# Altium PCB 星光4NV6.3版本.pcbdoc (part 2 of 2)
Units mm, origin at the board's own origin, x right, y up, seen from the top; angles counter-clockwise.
Board outline 96.4 x 47 mm, 2 copper layers (Top Layer, Bottom Layer), stack 1.58 mm thick; 27 components, 21 nets, 136 pads, 174 vias.
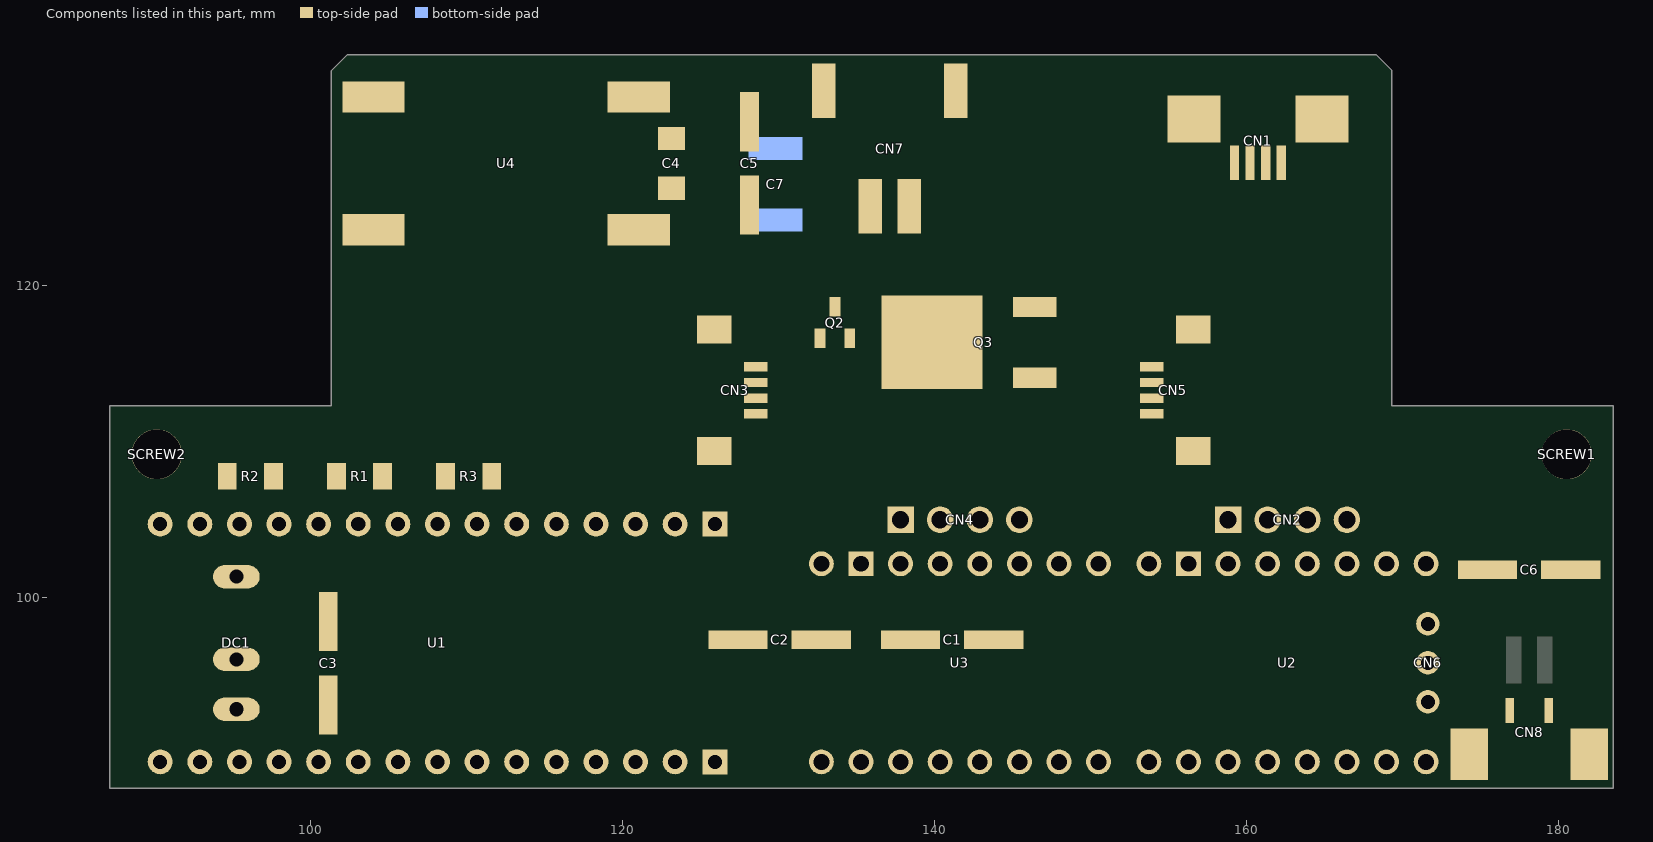
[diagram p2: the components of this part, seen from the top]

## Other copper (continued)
Bottom Layer:
  region net D8/EN: 100.302,105.766 100.702,105.766 100.704,105.713 100.711,105.665 100.722,105.622 100.736,105.583 100.754,105.548 100.776,105.516 100.827,105.458 100.888,105.403 100.955,105.347 101.027,105.283 101.102,105.206 99.902,105.206 99.977,105.283 100.049,105.347 100.116,105.403 100.177,105.458 100.228,105.516 100.25,105.548 100.268,105.583 100.282,105.622 100.293,105.665 100.3,105.713
  region net D2/X-STEP: 115.942,103.588 115.542,103.588 115.54,103.641 115.533,103.689 115.522,103.732 115.508,103.771 115.49,103.806 115.468,103.838 115.417,103.896 115.356,103.951 115.289,104.007 115.217,104.071 115.142,104.148 116.342,104.148 116.267,104.071 116.195,104.007 116.128,103.951 116.067,103.896 116.016,103.838 115.994,103.806 115.976,103.771 115.962,103.732 115.951,103.689 115.944,103.641
  region net D3/Y-STEP: 113.402,103.588 113.002,103.588 113,103.641 112.993,103.689 112.982,103.732 112.968,103.771 112.95,103.806 112.928,103.838 112.877,103.896 112.816,103.951 112.749,104.007 112.677,104.071 112.602,104.148 113.802,104.148 113.727,104.071 113.655,104.007 113.588,103.951 113.527,103.896 113.476,103.838 113.454,103.806 113.436,103.771 113.422,103.732 113.411,103.689 113.404,103.641
  region net 5V: 160.263,89.237 160.263,89.637 160.316,89.639 160.364,89.646 160.407,89.657 160.446,89.671 160.481,89.689 160.513,89.711 160.571,89.762 160.626,89.823 160.682,89.89 160.746,89.962 160.823,90.037 160.823,88.837 160.746,88.912 160.682,88.984 160.626,89.051 160.571,89.112 160.513,89.163 160.481,89.185 160.446,89.203 160.407,89.217 160.364,89.228 160.316,89.235
  region net 5V: 161.152,90.526 161.552,90.526 161.554,90.473 161.561,90.425 161.572,90.382 161.586,90.343 161.604,90.308 161.626,90.276 161.677,90.218 161.738,90.163 161.805,90.107 161.877,90.043 161.952,89.966 160.752,89.966 160.827,90.043 160.899,90.107 160.966,90.163 161.027,90.218 161.078,90.276 161.1,90.308 161.118,90.343 161.132,90.382 161.143,90.425 161.15,90.473
  region net 5V: 159.901,89.637 159.901,89.237 159.848,89.235 159.8,89.228 159.757,89.217 159.718,89.203 159.683,89.185 159.651,89.163 159.593,89.112 159.538,89.051 159.482,88.984 159.418,88.912 159.341,88.837 159.341,90.037 159.418,89.962 159.482,89.89 159.538,89.823 159.593,89.762 159.651,89.711 159.683,89.689 159.718,89.671 159.757,89.657 159.8,89.646 159.848,89.639
  region net 5V: 157.723,89.237 157.723,89.637 157.776,89.639 157.824,89.646 157.867,89.657 157.906,89.671 157.941,89.689 157.973,89.711 158.031,89.762 158.086,89.823 158.142,89.89 158.206,89.962 158.283,90.037 158.283,88.837 158.206,88.912 158.142,88.984 158.086,89.051 158.031,89.112 157.973,89.163 157.941,89.185 157.906,89.203 157.867,89.217 157.824,89.228 157.776,89.235
  region net 5V: 157.361,89.637 157.361,89.237 157.308,89.235 157.26,89.228 157.217,89.217 157.178,89.203 157.143,89.185 157.111,89.163 157.053,89.112 156.998,89.051 156.942,88.984 156.878,88.912 156.801,88.837 156.801,90.037 156.878,89.962 156.942,89.89 156.998,89.823 157.053,89.762 157.111,89.711 157.143,89.689 157.178,89.671 157.217,89.657 157.26,89.646 157.308,89.639
  region net 5V: 139.263,89.237 139.263,89.637 139.316,89.639 139.364,89.646 139.407,89.657 139.446,89.671 139.481,89.689 139.513,89.711 139.571,89.762 139.626,89.823 139.682,89.89 139.746,89.962 139.823,90.037 139.823,88.837 139.746,88.912 139.682,88.984 139.626,89.051 139.571,89.112 139.513,89.163 139.481,89.185 139.446,89.203 139.407,89.217 139.364,89.228 139.316,89.235
  region net 5V: 140.152,90.526 140.552,90.526 140.554,90.473 140.561,90.425 140.572,90.382 140.586,90.343 140.604,90.308 140.626,90.276 140.677,90.218 140.738,90.163 140.805,90.107 140.877,90.043 140.952,89.966 139.752,89.966 139.827,90.043 139.899,90.107 139.966,90.163 140.027,90.218 140.078,90.276 140.1,90.308 140.118,90.343 140.132,90.382 140.143,90.425 140.15,90.473
  region net 5V: 138.901,89.637 138.901,89.237 138.848,89.235 138.8,89.228 138.757,89.217 138.718,89.203 138.683,89.185 138.651,89.163 138.593,89.112 138.538,89.051 138.482,88.984 138.418,88.912 138.341,88.837 138.341,90.037 138.418,89.962 138.482,89.89 138.538,89.823 138.593,89.762 138.651,89.711 138.683,89.689 138.718,89.671 138.757,89.657 138.8,89.646 138.848,89.639
  region net 5V: 136.723,89.237 136.723,89.637 136.776,89.639 136.824,89.646 136.867,89.657 136.906,89.671 136.941,89.689 136.973,89.711 137.031,89.762 137.086,89.823 137.142,89.89 137.206,89.962 137.283,90.037 137.283,88.837 137.206,88.912 137.142,88.984 137.086,89.051 137.031,89.112 136.973,89.163 136.941,89.185 136.906,89.203 136.867,89.217 136.824,89.228 136.776,89.235
  region net 5V: 136.361,89.637 136.361,89.237 136.308,89.235 136.26,89.228 136.217,89.217 136.178,89.203 136.143,89.185 136.111,89.163 136.053,89.112 135.998,89.051 135.942,88.984 135.878,88.912 135.801,88.837 135.801,90.037 135.878,89.962 135.942,89.89 135.998,89.823 136.053,89.762 136.111,89.711 136.143,89.689 136.178,89.671 136.217,89.657 136.26,89.646 136.308,89.639
  region net 5V: 148.172,101.048 147.772,101.048 147.77,101.101 147.763,101.149 147.752,101.192 147.738,101.231 147.72,101.266 147.698,101.298 147.647,101.356 147.586,101.411 147.519,101.467 147.447,101.531 147.372,101.608 148.572,101.608 148.497,101.531 148.425,101.467 148.358,101.411 148.297,101.356 148.246,101.298 148.224,101.266 148.206,101.231 148.192,101.192 148.181,101.149 148.174,101.101
  region net $1N40669: 170.601,98.087 170.601,98.487 170.65,98.489 170.694,98.495 170.734,98.505 170.77,98.518 170.803,98.535 170.833,98.554 170.889,98.6 170.942,98.655 170.996,98.716 171.056,98.782 171.126,98.849 171.126,97.724 171.056,97.792 170.996,97.858 170.942,97.919 170.889,97.974 170.833,98.02 170.803,98.039 170.77,98.056 170.734,98.069 170.694,98.079 170.65,98.085
  region net 5V: 170.601,95.587 170.601,95.987 170.65,95.989 170.694,95.995 170.734,96.005 170.77,96.018 170.803,96.035 170.833,96.054 170.889,96.1 170.942,96.155 170.996,96.217 171.056,96.282 171.126,96.35 171.126,95.225 171.056,95.292 170.996,95.358 170.942,95.419 170.889,95.474 170.833,95.52 170.803,95.54 170.77,95.556 170.734,95.569 170.694,95.579 170.65,95.585
  region net $1N38622: 137.512,106.316 138.112,106.316 ccw(c138.625,106.316) 138.562,105.807 137.062,105.807 ccw(c136.999,106.316)
  region net $1N38620: 140.052,106.114 140.652,106.114 140.654,106.068 140.66,106.023 140.681,105.941 140.714,105.864 140.757,105.793 140.809,105.724 140.866,105.657 140.989,105.519 139.715,105.519 139.838,105.657 139.895,105.724 139.947,105.793 139.99,105.864 140.023,105.941 140.044,106.023 140.05,106.068
  region net $1N38619: 142.592,106.114 143.192,106.114 143.194,106.068 143.2,106.023 143.221,105.941 143.254,105.864 143.297,105.793 143.349,105.724 143.406,105.657 143.529,105.519 142.255,105.519 142.378,105.657 142.435,105.724 142.487,105.793 142.53,105.864 142.563,105.941 142.584,106.023 142.59,106.068
  region net $1N38618: 145.132,106.114 145.732,106.114 145.734,106.068 145.74,106.023 145.761,105.941 145.794,105.864 145.837,105.793 145.889,105.724 145.946,105.657 146.069,105.519 144.795,105.519 144.918,105.657 144.975,105.724 145.027,105.793 145.07,105.864 145.103,105.941 145.124,106.023 145.13,106.068
  region net 5V: 133.322,129.357 133.322,128.157 ccw(c133.322,116.718) 131.522,128.014 131.522,129.5 ccw(c133.322,140.796) 133.322,129.357
  region net $1N40367: 133.003,124.772 133.003,123.572 ccw(c133.003,115.803) 131.522,123.429 131.522,124.914 ccw(c133.003,132.541) 133.003,124.772
  region net D2/X-STEP: 120.846,96.215 121.129,96.498 121.17,96.451 121.205,96.41 121.223,96.394 121.244,96.381 121.27,96.372 121.3,96.367 120.977,96.043 120.972,96.074 120.963,96.099 120.95,96.12 120.933,96.139 120.893,96.174
  region net $1N38622: 152.4,114.457 152.4,115.057 152.766,115.062 152.766,114.452
  region net $1N38622: 152.333,115.057 152.333,114.457 151.967,114.452 151.967,115.062
  region net $1N38622: 151.601,114.457 151.601,115.057 151.967,115.062 151.967,114.452
  region net $1N38620: 152.333,114.057 152.333,113.457 151.967,113.452 151.967,114.062
  region net $1N38620: 151.601,113.457 151.601,114.057 151.967,114.062 151.967,113.452
  region net $1N38620: 152.4,113.457 152.4,114.057 152.766,114.062 152.766,113.452
  region net $1N38619: 151.601,112.457 151.601,113.057 151.967,113.062 151.967,112.452
  region net $1N38619: 152.333,113.057 152.333,112.457 151.967,112.452 151.967,113.062
  region net $1N38619: 152.4,112.457 152.4,113.057 152.766,113.062 152.766,112.452
  region net $1N38618: 151.601,111.457 151.601,112.057 151.967,112.062 151.967,111.452
  region net $1N38618: 152.333,112.057 152.333,111.457 151.967,111.452 151.967,112.062
  region net $1N38618: 152.4,111.457 152.4,112.057 152.766,112.062 152.766,111.452
  region net D8/EN: 100.702,107.788 100.302,107.788 100.3,107.854 100.292,107.919 100.274,107.98 100.259,108.008 100.24,108.033 100.765,108.033 100.745,108.008 100.73,107.98 100.712,107.919 100.704,107.854
  region net $1N40669: 152.219,103.979 151.819,103.979 151.823,104.041 151.827,104.094 151.826,104.119 151.82,104.143 151.809,104.167 151.79,104.192 152.248,104.192 152.229,104.167 152.218,104.143 152.212,104.119 152.211,104.094 152.215,104.041
  region net $1N40669: 151.819,104.809 152.219,104.809 152.215,104.747 152.211,104.694 152.212,104.669 152.218,104.645 152.229,104.621 152.248,104.596 151.79,104.596 151.809,104.621 151.82,104.645 151.826,104.669 151.827,104.694 151.823,104.747
  region net $1N40669: 152.219,104.733 151.819,104.733 151.823,104.795 151.827,104.848 151.826,104.873 151.82,104.897 151.809,104.921 151.79,104.946 152.248,104.946 152.229,104.921 152.218,104.897 152.212,104.873 152.211,104.848 152.215,104.795
  region net D3/Y-STEP: 113.747,96.229 114.03,96.512 114.071,96.465 114.106,96.424 114.125,96.408 114.146,96.395 114.171,96.386 114.202,96.381 113.878,96.057 113.873,96.088 113.864,96.113 113.851,96.134 113.835,96.153 113.794,96.188
  region net D3/Y-STEP: 114.617,95.924 114.335,95.642 114.294,95.688 114.259,95.729 114.24,95.745 114.219,95.758 114.194,95.768 114.163,95.772 114.487,96.096 114.491,96.065 114.501,96.04 114.514,96.019 114.53,96 114.571,95.965
  region net D3/Y-STEP: 114.46,95.517 114.742,95.799 114.783,95.753 114.818,95.712 114.837,95.696 114.858,95.683 114.883,95.673 114.914,95.669 114.59,95.345 114.586,95.376 114.576,95.401 114.563,95.422 114.547,95.441 114.506,95.476
  region net D2/X-STEP: 121.015,96.611 120.733,96.328 120.692,96.375 120.657,96.416 120.638,96.432 120.617,96.445 120.592,96.454 120.561,96.459 120.885,96.783 120.889,96.752 120.899,96.727 120.912,96.706 120.928,96.687 120.969,96.652
  region net D2/X-STEP: 120.145,96.916 120.428,97.198 120.469,97.152 120.504,97.111 120.522,97.095 120.544,97.082 120.569,97.072 120.599,97.068 120.276,96.744 120.271,96.775 120.262,96.8 120.249,96.821 120.233,96.84 120.192,96.875
  region net D8/EN: 100.302,107.718 100.702,107.718 100.698,107.656 100.694,107.603 100.695,107.578 100.701,107.554 100.712,107.53 100.731,107.505 100.273,107.505 100.292,107.53 100.303,107.554 100.309,107.578 100.31,107.603 100.306,107.656
  region net D8/EN: 100.702,106.888 100.302,106.888 100.306,106.95 100.31,107.003 100.309,107.028 100.303,107.052 100.292,107.077 100.273,107.101 100.731,107.101 100.712,107.077 100.701,107.052 100.695,107.028 100.694,107.003 100.698,106.95
  region net 12V: 129.921,99.152 cw(c129.921,100.608) 128.948,99.525 127.127,98.552 126.527,97.103 cw(c129.921,90.74) 129.921,97.952 129.921,99.152
  region net 12V: 127.924,103.798 cw(c117.797,103.798) 126.703,98.976 127.551,98.128 cw(c128.524,97.155) 129.497,98.128 130.345,98.976 cw(c139.251,103.798) 129.124,103.798
  region net 12V: 128.948,100.373 ccw(c132.012,103.437) 131.37,99.152 129.921,98.552 127.272,99.152 ccw(c127.272,100.256) 128.1,99.525
  region net 5V: 147.772,97.457 cw(c144.051,97.457) 147.444,95.929 147.727,95.646 cw(c147.972,95.4) 148.217,95.646 148.5,95.929 cw(c151.893,97.457) 148.172,97.457
  region net 5V: 148.113,96.315 ccw(c148.911,97.113) 148.842,95.987 148.359,95.787 147.585,95.987 ccw(c147.585,96.672) 147.831,96.033
  region net 5V: 148.113,96.033 ccw(c148.359,96.672) 148.359,95.987 147.585,95.787 147.102,95.987 ccw(c147.033,97.113) 147.831,96.315
  region net 5V: 161.552,94.128 cw(c165.335,94.128) 161.87,95.646 161.587,95.929 cw(c161.352,96.164) 161.117,95.929 160.834,95.646 cw(c157.369,94.128) 161.152,94.128
  region net 5V: 161.493,95.552 cw(c161.728,94.781) 161.728,95.587 160.976,95.787 160.493,95.587 cw(c160.44,94.499) 161.211,95.269
  region net 5V: 161.211,95.552 ccw(c160.976,94.781) 160.976,95.587 161.728,95.787 162.211,95.587 ccw(c162.264,94.499) 161.493,95.269

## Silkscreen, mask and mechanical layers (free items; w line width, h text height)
Top Silkscreen Layer:
  lines w0.254: 174.074,92.133 174.074,96.003 175.025,96.003 175.025,94.504 176.391,94.504 ; 177.853,94.504 178.391,94.504 ; 179.853,94.504 181.171,94.504 181.171,96.003 ; 182.122,92.133 182.122,96.003 181.171,96.003 ; 181.171,96.003 181.171,96.003 ; 181.171,96.003 181.171,96.003 ; 181.171,96.003 181.171,96.003
  text "X轴" at 165.713,126.746 h2
  text "0.1U" at 126.746,125.984 h2 r90
  text "220UF" at 131.191,125.603 h1.5 r90
  text "+" at 140.843,123.063 h3.05
  text "1mm-4P / 上接抽屉" at 160.401,122.428 h1.8
  text "Y轴" at 153.267,118.745 h2
  text "Y轴" at 128.375,115.951 h2
  text "3400" at 131.699,114.046 h1.5
  text "30N3P" at 138.557,111.125 h1.5
  text "1mm-4P / 下接翻盖" at 116.564,106.553 h1.8
  text "2B 2A 1A 1B" at 136.779,106.299 h1.5
  text "2B 2A 1A 1B" at 157.734,106.299 h1.5
  text "1mm-4P / 下接翻盖" at 149.352,104.775 h1.8
  text "Y轴" at 131.064,104.267 h3
  text "X轴" at 170.434,104.14 h3
  text "220UF" at 176.022,102.997 h1.5
  text "黄" at 162.03,97.282 h2
  text "Arduino nano" at 105.537,96.52 h2.8
  text "红" at 162.03,94.869 h2
  text "220UF" at 127.309,94.134 h1.5
  text "220UF" at 138.48,94.134 h1.5
  text "220UF" at 100.101,93.553 h1.5 r90
  text "黑" at 162.03,92.456 h2
  text "插反必烧" at 139.192,91.313 h2.2
  text "注意区分 / EN脚位" at 160.782,91.059 h2 r90
  text "舵机" at 161.036,90.932 h1.5
  text "EN" at 131.826,90.678 h3.05
  text "EN" at 152.781,90.678 h3.05
Bottom Silkscreen Layer:
  drawing of 81 lines, arcs and shapes, not listed
  text "备用激光测试" at 133.477,125.984 h1.2
  text "星光4N V6.3" at 165.608,124.079 h3.5
  text "必须调整电机驱动电位器（测电位器与GND / 之间电压），参考X轴0.32max，Y轴0.5max" at 167.64,114.554 h2.5
  text "【以上数据供参考，电机发热情况与 / 环境温度、工作加速度、最大速度、 / 负载阻力、连续工作时长等均有影响， / 若电机温度过高应休息冷却】" at 169.037,106.426 h1.8
  text "DC9-12V" at 112.014,99.949 h3
  text "注意区分EN脚方向！ / 必须调整电机驱动器的输出电流 / 防止输出过高导致电机高温、主板损坏" at 168.656,91.44 h2.5
Bottom Solder Mask Layer:
  text "流浪的星星" at 168.275,130.175 h4
Mechanical Layer:
  lines w0.003: 140.296,119.936 143.296,119.936 143.296,122.936 140.296,122.936 140.296,119.936 ; 147.322,119.936 150.322,119.936 150.322,122.936 147.322,122.936 147.322,119.936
